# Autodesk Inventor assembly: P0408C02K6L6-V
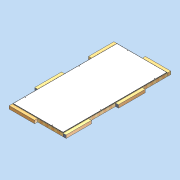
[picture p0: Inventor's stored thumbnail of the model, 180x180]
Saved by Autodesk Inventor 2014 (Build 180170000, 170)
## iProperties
Created: 2011-04
Part Number: P0408C02K6L6-V
Document SubType Name: Assembly
Designer: david.appleford
Description: 1w x 2w 02 Ceiling Panel  6 Lock 6 Lug
Mass: 54000 g
Surface Area: 70503.7 cm^2
Volume: 241970 cm^3
Density: 0.223168 g/cm^3
Cost Center: £171.00
Justset: False
Title: 1w x 2w 02 Ceiling Panel - 6 Locks 6 Lugs
Author: david.appleford
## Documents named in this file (4)
- C:\Documents and Settings\john.everitt\Local Settings\My Documents\Vault\Production MkII\VIRTUAL ELEMENTS\Virtual Ceilings\Ceiling MgO & Timber Frame\P0408C02K6L6-V.iam
- C:\Documents and Settings\john.everitt\Local Settings\My Documents\Vault\Production MkII\VIRTUAL ELEMENTS\Virtual Lugs\Superceded Lugs\LA02C3V.ipt
- C:\Documents and Settings\john.everitt\Local Settings\My Documents\Vault\Production MkII\VIRTUAL ELEMENTS\Virtual Lugs\Superceded Lugs\LA02M3V.ipt
- C:\Documents and Settings\john.everitt\Local Settings\My Documents\Vault\Production MkII\VIRTUAL ELEMENTS\Virtual Ceilings\Ceiling MgO & Timber Frame\P0408C02K6-V.ipt
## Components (7 placed, 3 different names)
1. P0408C02K6-V:1 — Mate:1, Flush:1, Flush:2, Mate:2, Flush:3, Flush:4, Mate:4, Flush:7, Flush:8, Mate:5, Mate:6, Flush:9, Flush:10, Mate:7, Flush:11
2. LA02C3V:1 — Mate:1, Flush:1, Flush:2, Mate:9, Mate:13
3. LA02C3V:2 — Mate:2, Flush:3, Flush:4
4. LA02C3V:3 — Mate:4, Flush:7, Flush:8
5. LA02C3V:4 — Mate:6, Flush:9, Mate:12
6. LA02M3V:2 — Mate:5, Flush:10, Mate:12, Mate:13
7. LA02M3V:4 — Mate:7, Flush:11, Mate:9
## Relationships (18: Mate 9, Flush 9)
- Mate:1: P0408C02K6-V:1 ↔ LA02C3V:1
- Flush:1: P0408C02K6-V:1 ↔ LA02C3V:1
- Flush:2: P0408C02K6-V:1 ↔ LA02C3V:1
- Mate:2: P0408C02K6-V:1 ↔ LA02C3V:2
- Flush:3: P0408C02K6-V:1 ↔ LA02C3V:2
- Flush:4: P0408C02K6-V:1 ↔ LA02C3V:2
- Mate:4: P0408C02K6-V:1 ↔ LA02C3V:3
- Flush:7: P0408C02K6-V:1 ↔ LA02C3V:3
- Flush:8: P0408C02K6-V:1 ↔ LA02C3V:3
- Mate:5: P0408C02K6-V:1 ↔ LA02M3V:2
- Mate:6: P0408C02K6-V:1 ↔ LA02C3V:4
- Flush:9: P0408C02K6-V:1 ↔ LA02C3V:4
- Flush:10: P0408C02K6-V:1 ↔ LA02M3V:2
- Mate:7: P0408C02K6-V:1 ↔ LA02M3V:4
- Flush:11: P0408C02K6-V:1 ↔ LA02M3V:4
- Mate:9: LA02C3V:1 ↔ LA02M3V:4
- Mate:12: LA02C3V:4 ↔ LA02M3V:2
- Mate:13: LA02C3V:1 ↔ LA02M3V:2
## Named parameters: t = 1 mm, Cl = 2 mm
